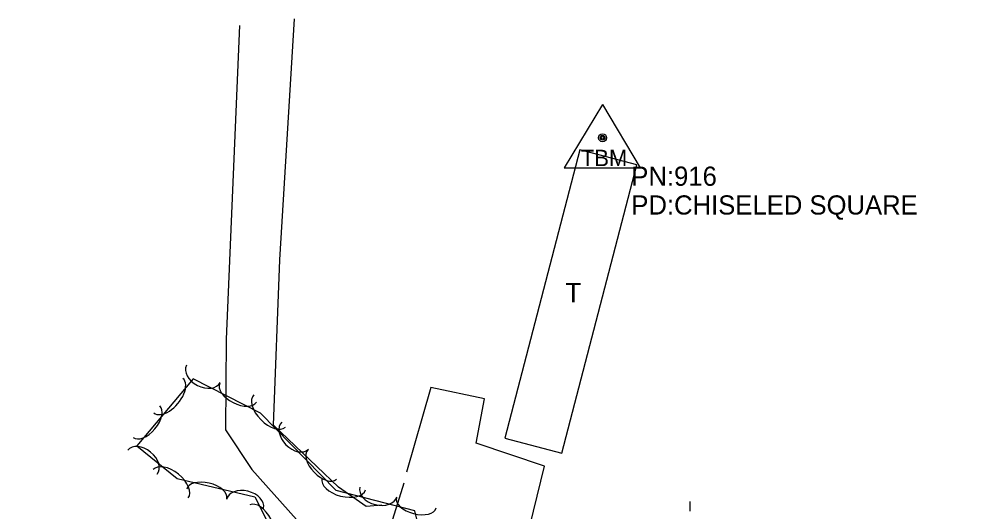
# Model space of a CAD drawing. Extents: x 1441650 to 1491889, y 345904 to 358319.
# Drawn here: x 1448359.4 to 1448606.3, y 354008 to 354136.2 of the extents above; entities that cross this region are included whole.
import ezdxf

# ---------------------------------------------------------------- set-up
doc = ezdxf.new("R2010")
doc.units = 0
for name, color, linetype in [('S_BUILDING', 7, 'Continuous'), ('S_BUILDING_ANNOT', 7, 'Continuous'), ('S_GRAVEL_ROAD', 7, 'Continuous'), ('S_PARKING', 7, 'Continuous'), ('S_PRIMARY_CTL', 7, 'Continuous'), ('S_PRIMARY_CTL_ANNOT', 7, 'Continuous'), ('S_TREE', 7, 'Continuous'), ('S_UTILITY_POLE', 7, 'Continuous')]:
    doc.layers.add(name, color=color, linetype=linetype)

msp = doc.modelspace()

# ---------------------------------------------------------------- linework, layer by layer
at = {"layer": 'S_BUILDING'}
msp.add_lwpolyline([(1448505.62, 354102.1), (1448486.03, 354026.98), (1448500.89, 354023.11), (1448520.48, 354098.23)], close=True, dxfattribs=at)
at = {"layer": 'S_GRAVEL_ROAD'}
msp.add_lwpolyline([(1448459.67, 354015.23), (1448455.01, 354000.28), (1448450.35, 353985.34), (1448442.7, 353968.16), (1448435.05, 353950.98), (1448425.99, 353939.21), (1448419.04, 353931.32)], dxfattribs=at)
at = {"layer": 'S_PARKING'}
for points in [[(1448453.98, 354009.58), (1448449.93, 354009.21), (1448442.72, 354014.2), (1448425.73, 354030.34), (1448427.38, 354073.49), (1448431.21, 354136.21)], [(1448416.84, 354134.5), (1448413.4, 354052.78), (1448413.19, 354029.14), (1448420.09, 354018.8), (1448431.69, 354005.8), (1448444.56, 353995.24), (1448446.03, 353983.46)], [(1448465.2, 353976.95), (1448469.53, 353983.6), (1448488.84, 353988.82), (1448496.37, 354019.74), (1448478.58, 354025.69), (1448480.78, 354037.21), (1448466.76, 354040.18), (1448460.39, 354018.12)]]:
    msp.add_lwpolyline(points, dxfattribs=at)
at = {"layer": 'S_PRIMARY_CTL'}
for p, q in [((1448511.52, 354113.95), (1448501.49, 354097.44)), ((1448511.52, 354113.95), (1448521.34, 354097.44)), ((1448501.49, 354097.44), (1448521.34, 354097.44))]:
    msp.add_line(p, q, dxfattribs=at)
for radius in [1.04, 0.609, 0.344]:
    msp.add_circle((1448511.52, 354105.25), radius, dxfattribs=at)
at = {"layer": 'S_TREE'}
msp.add_lwpolyline([(1448626.95, 353920.34), (1448580.91, 353934.22), (1448558.39, 353944.23), (1448529.51, 353950.57), (1448499.52, 353957.04), (1448473.09, 353965.35), (1448462.54, 354008.07), (1448442.1, 354013.35), (1448422.32, 354033.48), (1448404.79, 354042.44), (1448390.08, 354024.99), (1448400.64, 354016.45), (1448420.88, 354011.71), (1448432.24, 353989.15), (1448430.84, 353958.62), (1448421.04, 353945.8), (1448313.04, 353969.02)], dxfattribs=at)
for centre, major_axis, ratio, start_param, end_param in [((1448407.44, 354043.76), (4.41, -2.25), 0.685309, 3.141593, 6.283185), ((1448398.33, 354038.07), (3.78, 4.49), 0.5501, 3.141597, 6.28319), ((1448416.5, 354038.84), (4.76, -2.43), 0.540698, 3.141593, 6.283185), ((1448424.71, 354034.08), (4.11, -4.19), 0.550078, 3.141593, 6.283185), ((1448392.62, 354031.3), (3.45, 4.09), 0.540719, 3.141597, 6.283189), ((1448431.38, 354027.66), (3.47, -3.54), 0.685309, 3.141593, 6.283185), ((1448391.57, 354020.72), (-3.85, 3.12), 0.685309, 3.141593, 6.283185), ((1448438.41, 354020.13), (3.75, -3.81), 0.540698, 3.141593, 6.283185), ((1448398.93, 354015.1), (-4.56, 3.69), 0.550078, 3.141593, 6.283185), ((1448408.32, 354012.47), (-5.21, 1.22), 0.540698, 3.141593, 6.283185), ((1448444.03, 354015.04), (5.68, -1.47), 0.550078, 3.141593, 6.283185), ((1448418.3, 354009.87), (-4.82, 1.13), 0.685309, 3.141593, 6.283185), ((1448453.06, 354012.98), (4.8, -1.24), 0.685309, 3.141593, 6.283185), ((1448422.2, 354004.36), (-2.64, 5.24), 0.550079, 3.141593, 6.283185), ((1448462.97, 354010.15), (5.18, -1.34), 0.540698, 3.141593, 6.283185)]:
    msp.add_ellipse(centre, major_axis=major_axis, ratio=ratio, start_param=start_param, end_param=end_param, dxfattribs=at)
at = {"layer": 'S_UTILITY_POLE'}
msp.add_line((1448534.34, 354008.02), (1448534.34, 354010.5), dxfattribs=at)

# ---------------------------------------------------------------- texts
at = {"layer": 'S_BUILDING_ANNOT'}
msp.add_text('T', height=5, dxfattribs=at).set_placement((1448501.86, 354062.42))
at = {"layer": 'S_PRIMARY_CTL'}
msp.add_text('TBM', height=4.287, rotation=360, dxfattribs=at).set_placement((1448505.87, 354097.86))
at = {"layer": 'S_PRIMARY_CTL_ANNOT'}
for s, p in [('PN:916', (1448519.02, 354092.75)), ('PD:CHISELED SQUARE', (1448519.02, 354085.25))]:
    msp.add_text(s, height=5, dxfattribs=at).set_placement(p)

doc.saveas('drawing.dxf')
